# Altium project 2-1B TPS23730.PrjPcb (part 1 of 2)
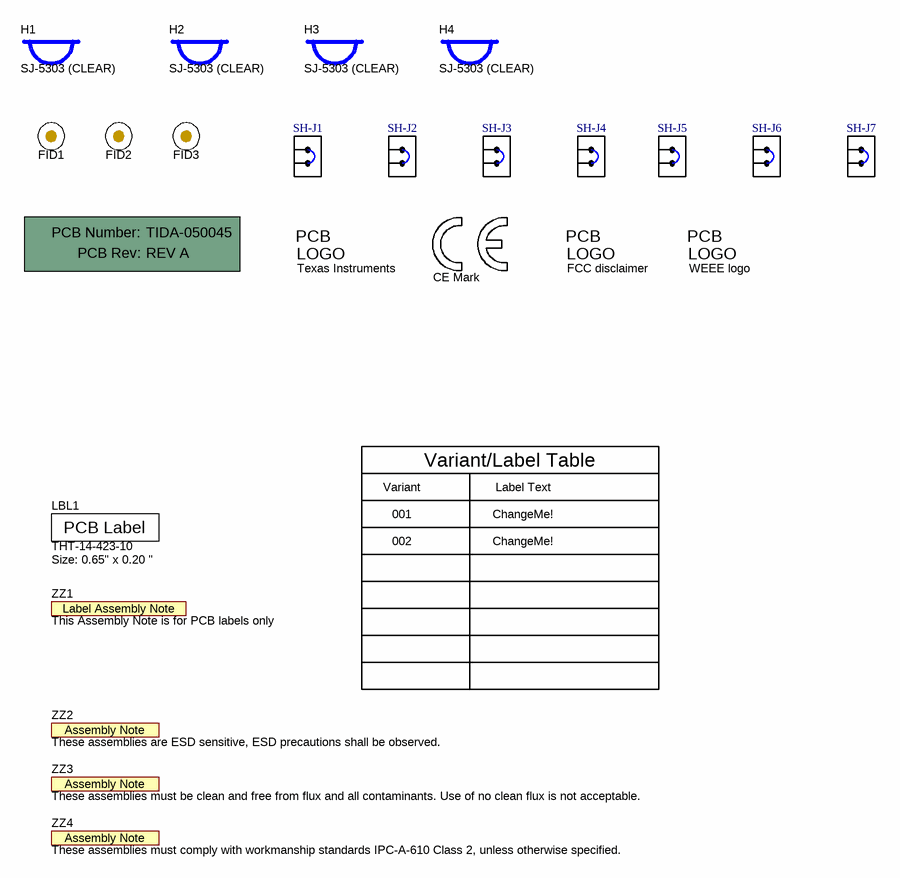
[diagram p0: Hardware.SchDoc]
CopyrightYear: 2020; PCB_Layout: Michael Pahl; PCB_Rev: REV A; PRJ_Customer: Public Release; PRJ_Engineer: Michael Pahl; PRJ_Number: TIDA-050045; PRJ_Title: Type 3 IEEE802.3bt-ready ACF PoE PD; SCH_Rev: A; TechSupport: http://www.ti.com/support; TID: TIDA-050045
3 sheets, 250 parts. Net scope: global (net labels, ports and power ports of the same name join across sheets).
Board file: PCB.PcbDoc
Sheets:
  Hardware.SchDoc
  Power Stage.SchDoc
  TPS23730 Page 1 Input Power.SchDoc

## Sheet Hardware.SchDoc
size 431 x 279 mm; Date: Not shown in title block; ApprovedBy: Not shown in title block; CheckedBy: Not shown in title block; Author: Not shown in title block; CompanyName: Not shown in title block; Engineer: Not shown in title block; Organization: Not shown in title block; Address1: Not shown in title block; Address2: Not shown in title block; Address3: Not shown in title block; Address4: Not shown in title block; DocumentNumber: 3; Revision: Use project parameter SCH_Rev; SheetNumber: 3; SheetTotal: 3; PageSetup: Record=PageOptions¦CenterHorizontal=True¦CenterVertical=True¦PrintScale=1.00¦XCorrection=1.00¦YCorrection=1.00¦PrintKind=0¦BorderSize=5000000¦LeftOffset=0¦BottomOffset=0¦Orientation=2¦PaperLength=1000¦PaperWidth=1000¦Scale=100¦PaperSource=15¦PrintQuality=600¦MediaType=1¦DitherType=10¦PaperKind=Letter¦PrintScaleMode=1

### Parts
!PCB1  Printed Circuit Board  (value not drawn)  (mechanical)
FID1  Fiducial  [Fiducial10-20]  (value not drawn)
FID2  Fiducial  [Fiducial10-20]  (value not drawn)
FID3  Fiducial  [Fiducial10-20]  (value not drawn)
H1  SJ-5303 (CLEAR)  [Bumpon_SJ5003Transparent]
H2  SJ-5303 (CLEAR)  [Bumpon_SJ5003Transparent]
H3  SJ-5303 (CLEAR)  [Bumpon_SJ5003Transparent]
H4  SJ-5303 (CLEAR)  [Bumpon_SJ5003Transparent]
LBL1  THT-14-423-10  Note: Size: 0.65" x 0.20 "  [Label_650x200]
Logo1  CE Mark  [CE_Mark_5mm]  (no BOM)
Logo2  Texas Instruments  [TI_Stacked_Overlay_Small]  (no BOM)
Logo3  FCC disclaimer  [FCC_disclaimer]  (no BOM)
Logo4  WEEE logo  [WEEE_Minimum]  (no BOM)
SH-J1  60900213421  [Wurth_60900213421]  (value not drawn)
SH-J2  60900213421  [Wurth_60900213421]  (value not drawn)
SH-J3  60900213421  [Wurth_60900213421]  (value not drawn)
SH-J4  60900213421  [Wurth_60900213421]  (value not drawn)
SH-J5  60900213421  [Wurth_60900213421]  (value not drawn)
SH-J6  60900213421  [Wurth_60900213421]  (value not drawn)
SH-J7  60900213421  [Wurth_60900213421]  (value not drawn)
ZZ1  This Assembly Note is for PCB labels only  [AssemblyNoteLabel]  (no BOM)
ZZ2  These assemblies are ESD sensitive, ESD precautions shall be observed.  [AssemblyNote]  (no BOM)
ZZ3  These assemblies must be clean and free from flux and all contaminants. Use of no clean flux is not acceptable.  [AssemblyNote]  (no BOM)
ZZ4  These assemblies must comply with workmanship standards IPC-A-610 Class 2, unless otherwise specified.  [AssemblyNote]  (no BOM)

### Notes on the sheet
- Variant
- Variant/Label Table
- Label Text
- 001
- 002
- ChangeMe!

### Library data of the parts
!PCB1 = CMP-0003618-2: Manufacturer: Any; PartNumber: TIDA-050045
FID1-FID3 = CMP-0077181-1: Fiducial mark.  There is nothing to buy or mount.
H1-H4 = CMP-0003620-1: Bumpon, Hemisphere, 0.44 X 0.20, Clear; Manufacturer: 3M
LBL1 = CMP-0003625-1: Thermal Transfer Printable Labels, 0.650" W x 0.200" H - 10,000 per roll; Manufacturer: Brady; CompType: Label
Logo1 = CMP-0074844-1: SymbolCreator: a0412235
Logo2 = CMP-0074838-1: Texas Instrument Corporate Signature; SymbolCreator: a0412235; Lib Reference: TI_Logo; Library Reference: Logo
Logo3 = CMP-0074847-1: FCC_disclaimer; Library Reference: Logo
Logo4 = CMP-0074769-1
SH-J1-SH-J7 = CMP-0003761-2: Shunt, 2.54mm, Gold, Black; Manufacturer: Wurth Elektronik
ZZ1 = CMP-0003616-3
ZZ2 = CMP-0077236-1
ZZ3 = CMP-0077237-1
ZZ4 = CMP-0077238-1

## Sheet Power Stage.SchDoc
size A2; Date: Not shown in title block; ApprovedBy: Not shown in title block; CheckedBy: Not shown in title block; Author: Not shown in title block; CompanyName: Not shown in title block; Engineer: Not shown in title block; Organization: Not shown in title block; Address1: Not shown in title block; Address2: Not shown in title block; Address3: Not shown in title block; Address4: Not shown in title block; DocumentNumber: 2; Revision: Use project parameter SCH_Rev; SheetNumber: 2; SheetTotal: 3; PageSetup: Record=PageOptions¦CenterHorizontal=True¦CenterVertical=True¦PrintScale=1.00¦XCorrection=1.00¦YCorrection=1.00¦PrintKind=0¦BorderSize=5000000¦LeftOffset=0¦BottomOffset=0¦Orientation=2¦PaperLength=1000¦PaperWidth=1000¦Scale=100¦PaperSource=15¦PrintQuality=600¦MediaType=1¦DitherType=10¦PaperKind=Letter¦PrintScaleMode=1
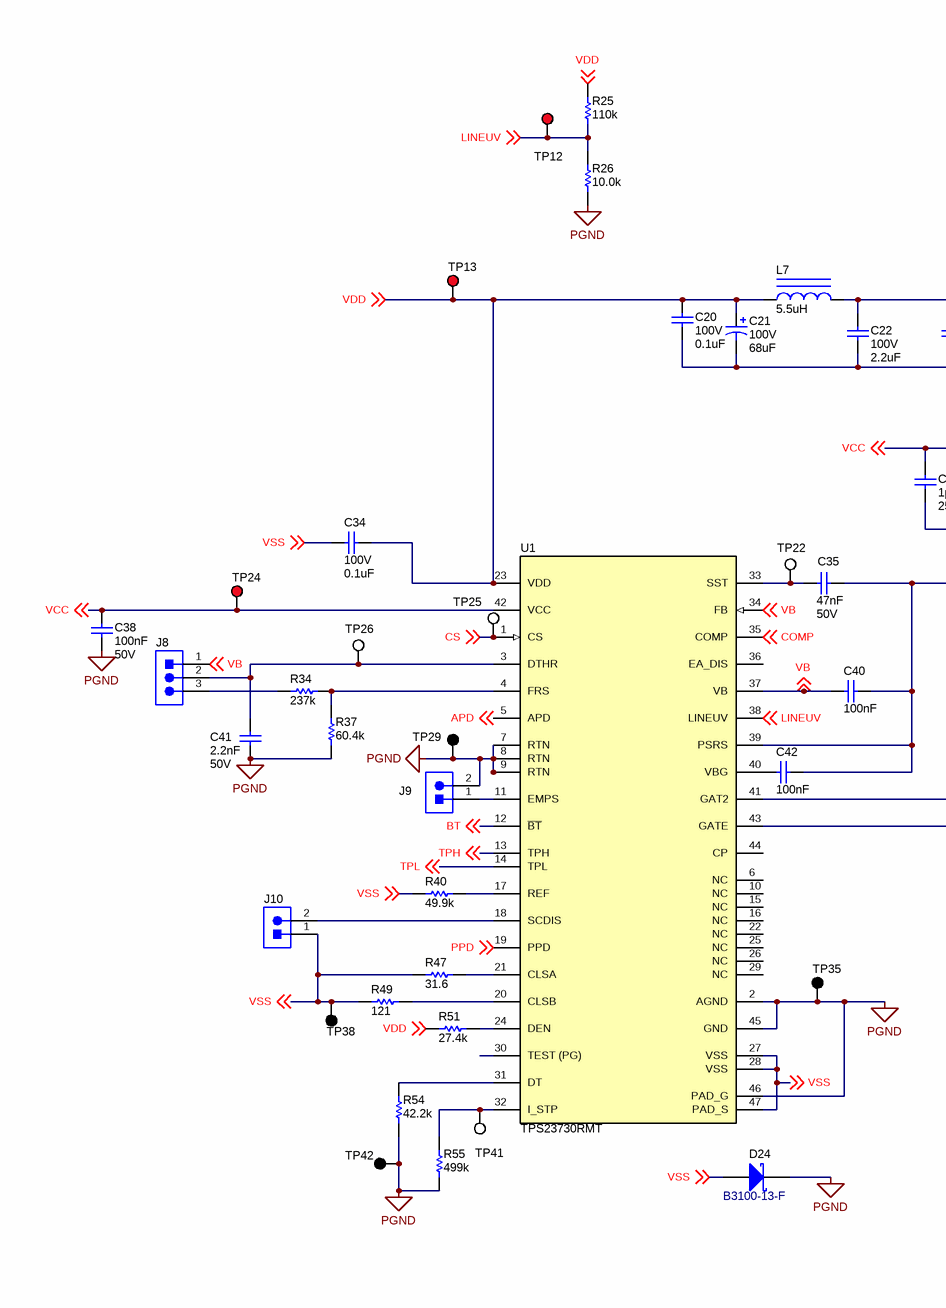
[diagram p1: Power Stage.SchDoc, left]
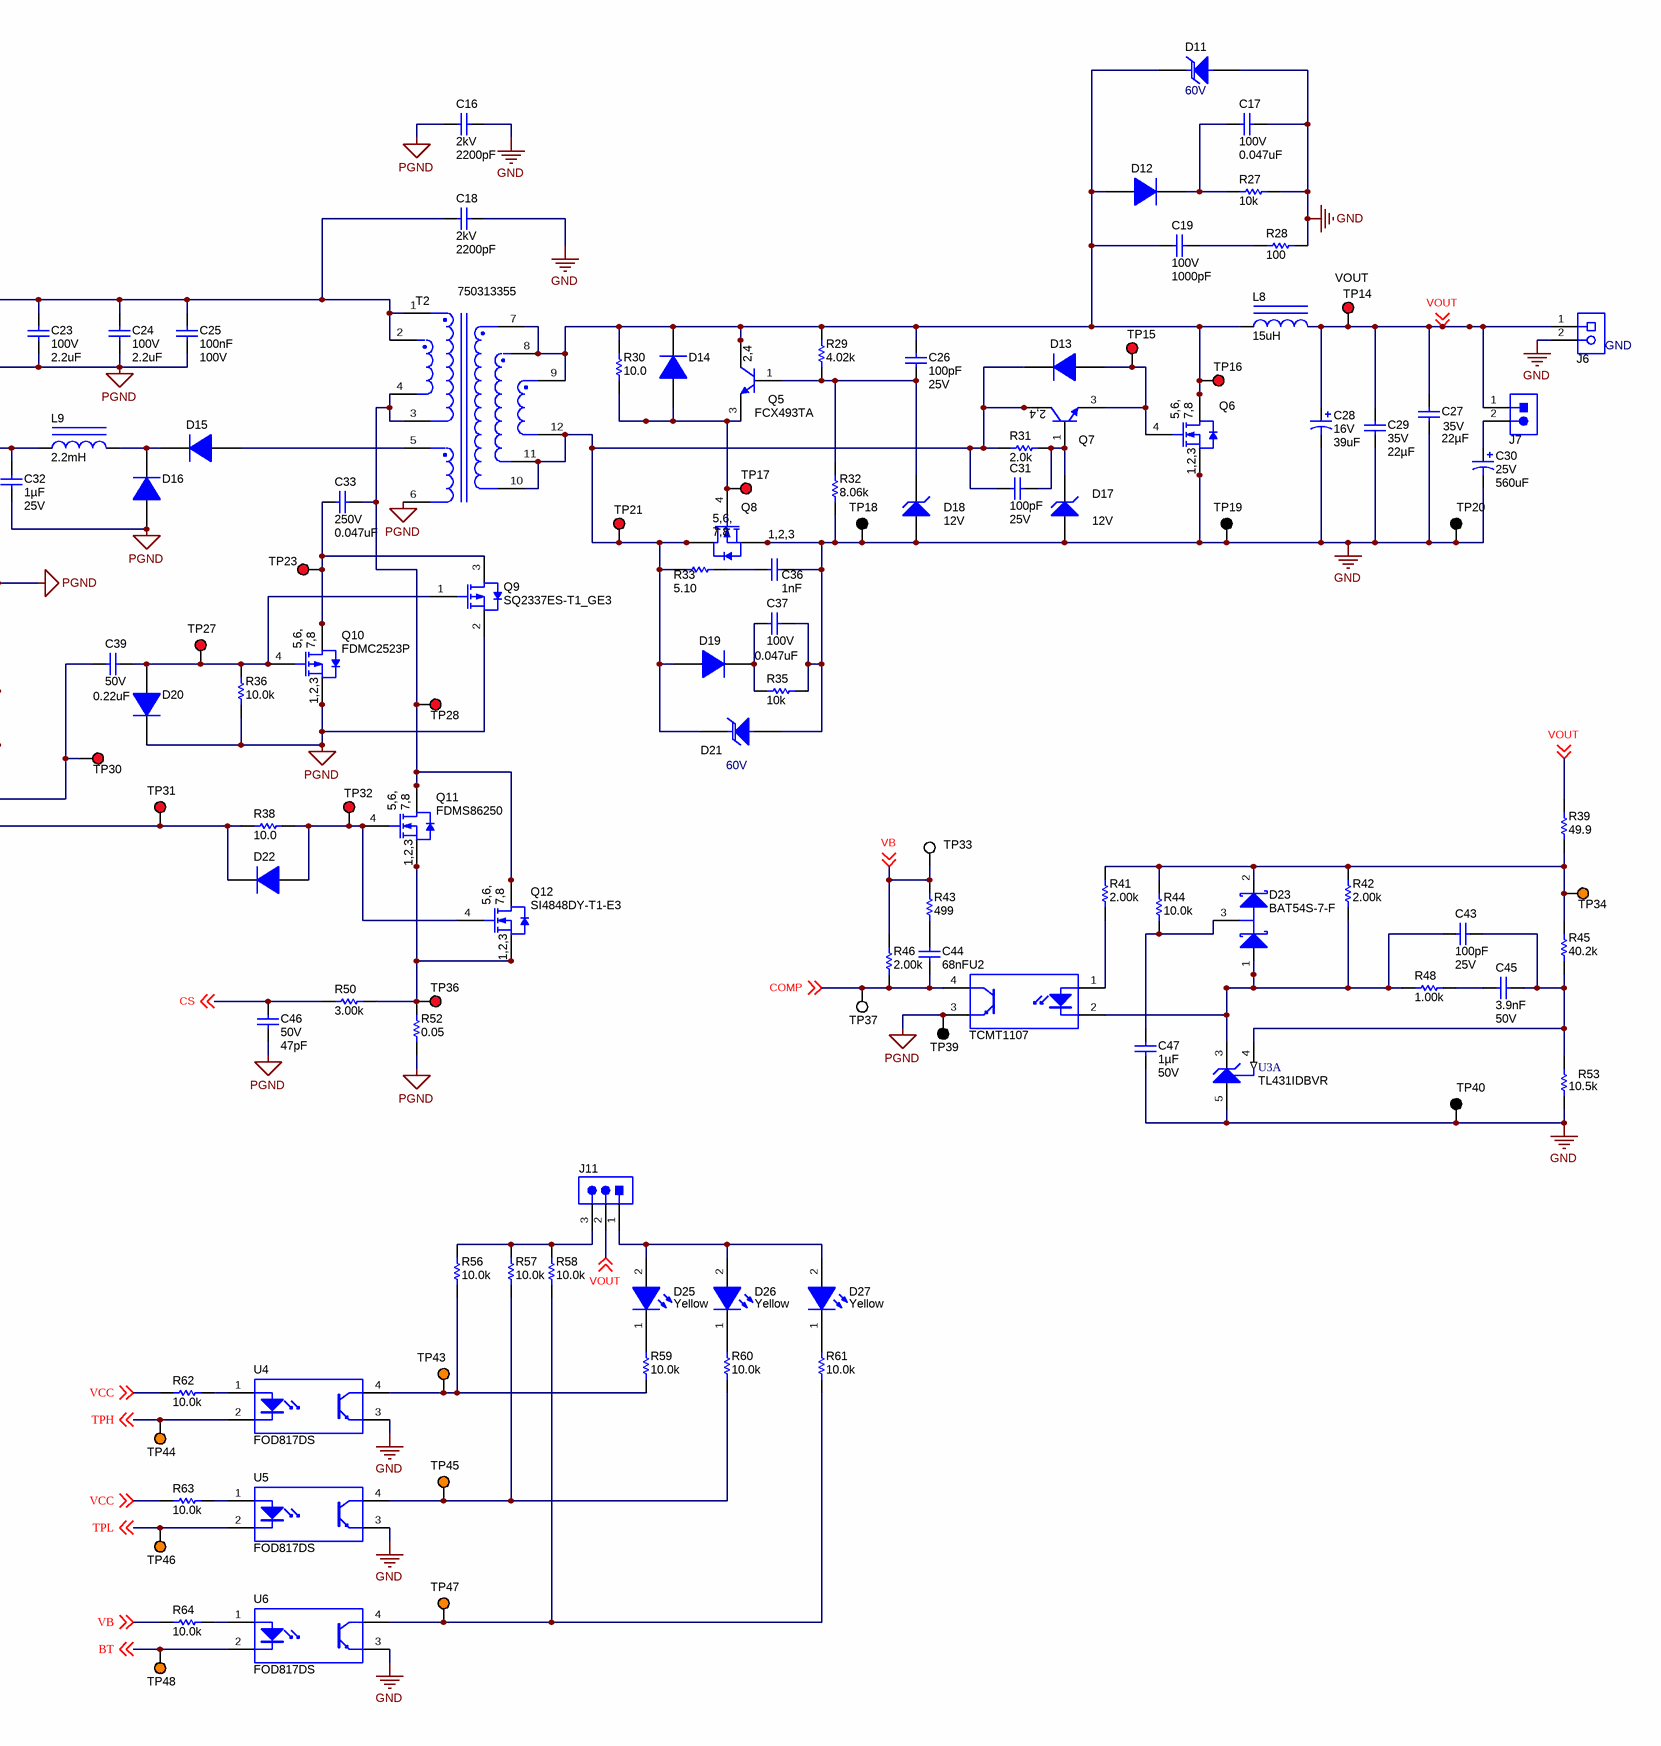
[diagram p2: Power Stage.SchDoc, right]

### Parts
C16  VDC_V: 2kV  ValueDisplayed: 2200pF  [1812_HV]  (hidden comment: C4532X7R3D222K130KA)
C17  VDC_V: 100V  ValueDisplayed: 0.047uF  [1206]  (hidden comment: CGA5H2X7R2A473K115AA)
C18  VDC_V: 2kV  ValueDisplayed: 2200pF  [1812_HV]  (hidden comment: C4532X7R3D222K130KA)
C19  VDC_V: 100V  ValueDisplayed: 1000pF  [1206]  (hidden comment: 12061C102KAT2A)
C20  VDC_V: 100V  ValueDisplayed: 0.1uF  [1206]  (hidden comment: GRM319R72A104KA01D)
C21  VDC_V: 100V  ValueDisplayed: 68uF  [SM_RADIAL_H13]  (hidden comment: EEV-FK2A680Q)
C22  VDC_V: 100V  ValueDisplayed: 2.2uF  [1210_270]  (hidden comment: GRM32ER72A225KA35L)
C23  VDC_V: 100V  ValueDisplayed: 2.2uF  [1210_270]  (hidden comment: GRM32ER72A225KA35L)
C24  VDC_V: 100V  ValueDisplayed: 2.2uF  [1210_270]  (hidden comment: GRM32ER72A225KA35L)
C25  Cap_F: 100nF  VDC_V: 100V  [0805_HV]  (hidden comment: GRM21BR72A104KAC4L)
C26  Cap_F: 100pF  VDC_V: 25V  [0603]  (hidden comment: 06033C101KAT2A)
C27  VDC_V: 35V  ValueDisplayed: 22µF  [1210]  (hidden comment: GMK325BJ226MM-P)
C28  VDC_V: 16V  ValueDisplayed: 39uF  [SM_RADIAL_6.3AMM]  (hidden comment: 16SVP39M)
C29  VDC_V: 35V  ValueDisplayed: 22µF  [1210]  (hidden comment: GMK325BJ226MM-P)
C30  VDC_V: 25V  ValueDisplayed: 560uF  [Panasonic_G]  (hidden comment: EEEFPE561UAP)
C31  Cap_F: 100pF  VDC_V: 25V  [0603]  (hidden comment: 06033C101KAT2A)
C32  Cap_F: 1µF  VDC_V: 25V  [0805_HV]  (hidden comment: GRM21BR71E105KA99L)
C33  VDC_V: 250V  ValueDisplayed: 0.047uF  [1206_180]  (hidden comment: GRM31CR72E473KW03L)
C34  VDC_V: 100V  ValueDisplayed: 0.1uF  [1206]  (hidden comment: GRM319R72A104KA01D)
C35  Cap_F: 47nF  VDC_V: 50V  [0603]  (hidden comment: GRM188R71H473KA61D)
C36  Cap_F: 1nF  [0603]  (hidden comment: CGA3E2X7R2A102K080AA)
C37  VDC_V: 100V  ValueDisplayed: 0.047uF  [1206]  (hidden comment: CGA5H2X7R2A473K115AA)
C38  Cap_F: 100nF  VDC_V: 50V  [0805_HV]  (hidden comment: GCM21BR71H104KA37K)
C39  VDC_V: 50V  ValueDisplayed: 0.22uF  [0805_HV]  (hidden comment: C2012X5R1H224K125AA)
C40  Cap_F: 100nF  [0603]  (hidden comment: CGA3E2X7R1E104K080AA)
C41  Cap_F: 2.2nF  VDC_V: 50V  [0603]  (hidden comment: C0603C222K5RAC)
C42  Cap_F: 100nF  [0603]  (hidden comment: C0603C104J3RACTU)
C43  Cap_F: 100pF  VDC_V: 25V  [0603]  (hidden comment: 06033C101KAT2A)
C44  Cap_F: 68nF  [0603]  (hidden comment: GRM188R71C683KA01D)
C45  Cap_F: 3.9nF  VDC_V: 50V  [0603]  (hidden comment: GRM188R71H392KA01D)
C46  VDC_V: 50V  ValueDisplayed: 47pF  [0603]  (hidden comment: GRM1885C1H470JA01D)
C47  Cap_F: 1µF  VDC_V: 50V  [0805_HV]  (hidden comment: C2012X7R1H105K125AB)
D11  value 60V  [SMC]  (hidden comment: SMCJ60A)
D12  MURA110T3G  [SMA]  (value not drawn)
D13  MMSD914T1G  [SOD-123]  (value not drawn)
D14  MMSD914T1G  [SOD-123]  (value not drawn)
D15  MMSD914T1G  [SOD-123]  (value not drawn)
D16  MMSD914T1G  [SOD-123]  (value not drawn)
D17  value 12V  [SOD-123]  (hidden comment: MMSZ5242B-7-F)
D18  value 12V  [SOD-123]  (hidden comment: MMSZ5242B-7-F)
D19  MURA110T3G  [SMA]  (value not drawn)
D20  MMSD914T1G  [SOD-123]  (value not drawn)
D21  value 60V  [SMC]  (hidden comment: SMCJ60A)
D22  MMSD914T1G  [SOD-123]  (value not drawn)
D23  BAT54S-7-F  [SOT-23]
D24  B3100-13-F  [SMC]
D25  value Yellow  [WL-SMCW_YELLOW]  (hidden comment: 150060YS75000)
D26  value Yellow  [WL-SMCW_YELLOW]  (hidden comment: 150060YS75000)
D27  value Yellow  [WL-SMCW_YELLOW]  (hidden comment: 150060YS75000)
J6  ED555/2DS  [TERM_BLK_ED555-2DS]  (value not drawn)
J7  5-146278-2  [TE_5-146278-2]  (value not drawn)
J8  5-146278-3  [TE_5-146278-3]  (value not drawn)
J9  5-146278-2  [TE_5-146278-2]  (value not drawn)
J10  5-146278-2  [TE_5-146278-2]  (value not drawn)
J11  5-146278-3  [TE_5-146278-3]  (value not drawn)
L7  ValueDisplayed: 5.5uH  [WE-HC6]  (hidden comment: 744325550)
L8  ValueDisplayed: 15uH  [WE-HCB_1890]  (hidden comment: 74435571500)
L9  ValueDisplayed: 2.2mH  [WE-PD2-L]  (hidden comment: 768775322)
Q5  FCX493TA  [SOT-89-3]
Q6  BSC105N10LSF G  [PG-TDSON-8]  (value not drawn)
Q7  FCX493TA  [SOT-89-3]  (value not drawn)
Q8  BSC105N10LSF G  [PG-TDSON-8]  (value not drawn)
Q9  SQ2337ES-T1_GE3  [SOT-23]
Q10  FDMC2523P  [MLP08S]
Q11  FDMS86250  [TRANS_Fairchild_PQFN08A]
Q12  SI4848DY-T1-E3  [SOIC-8]
R25  ValueDisplayed: 110k  [0603]  (hidden comment: CRCW0603110KFKEA)
R26  ValueDisplayed: 10.0k  [0603]  (hidden comment: CRCW060310K0FKEA)
R27  ValueDisplayed: 10k  [2512]  (hidden comment: CRCW251210K0JNEG)
R28  ValueDisplayed: 100  [2512]  (hidden comment: CRCW2512100RJNEG)
R29  ValueDisplayed: 4.02k  [1206]  (hidden comment: CRCW12064K02FKEA)
R30  ValueDisplayed: 10.0  [0603]  (hidden comment: CRCW060310R0FKEAHP)
R31  ValueDisplayed: 2.0k  [0603]  (hidden comment: CRCW06032K00JNEA)
R32  ValueDisplayed: 8.06k  [1206]  (hidden comment: CRCW12068K06FKEA)
R33  ValueDisplayed: 5.10  [0805_HV]  (hidden comment: ERJ-6RQF5R1V)
R34  ValueDisplayed: 237k  [0603]  (hidden comment: RC0603FR-07237KL)
R35  ValueDisplayed: 10k  [2512]  (hidden comment: CRCW251210K0JNEG)
R36  ValueDisplayed: 10.0k  [0603]  (hidden comment: CRCW060310K0FKEA)
R37  ValueDisplayed: 60.4k  [0603]  (hidden comment: CRCW060360K4FKEA)
R38  ValueDisplayed: 10.0  [0603]  (hidden comment: CRCW060310R0FKEA)
R39  ValueDisplayed: 49.9  [0603]  (hidden comment: RC0603FR-0749R9L)
R40  ValueDisplayed: 49.9k  [0603]  (hidden comment: CRCW060349K9FKEA)
R41  ValueDisplayed: 2.00k  [0603]  (hidden comment: CRCW06032K00FKEA)
R42  ValueDisplayed: 2.00k  [VSMP_0603]  (hidden comment: Y16362K00000F9R)
R43  ValueDisplayed: 499  [0603]  (hidden comment: CRCW0603499RFKEA)
R44  ValueDisplayed: 10.0k  [0603]  (hidden comment: CRCW060310K0FKEA)
R45  ValueDisplayed: 40.2k  [0603]  (hidden comment: CRCW060340K2FKEA)
R46  ValueDisplayed: 2.00k  [0603]  (hidden comment: CRCW06032K00FKEA)
R47  ValueDisplayed: 31.6  [0805_HV]  (hidden comment: CRCW080531R6FKEA)
R48  ValueDisplayed: 1.00k  [0603]  (hidden comment: CRCW06031K00FKEA)
R49  ValueDisplayed: 121  [0805_HV]  (hidden comment: CRCW0805121RFKEA)
R50  ValueDisplayed: 3.00k  [0603]  (hidden comment: RC0603FR-073KL)
R51  ValueDisplayed: 27.4k  [0603]  (hidden comment: RC0603FR-0727K4L)
R52  ValueDisplayed: 0.05  [1206]  (hidden comment: ERJ-8CWFR050V)
R53  ValueDisplayed: 10.5k  [0603]  (hidden comment: CRCW060310K5FKEA)
R54  ValueDisplayed: 42.2k  [0603]  (hidden comment: CRCW060342K2FKEA)
R55  ValueDisplayed: 499k  [0603]  (hidden comment: CRCW0603499KFKEA)
R56  ValueDisplayed: 10.0k  [0603]  (hidden comment: CRCW060310K0FKEA)
R57  ValueDisplayed: 10.0k  [0603]  (hidden comment: CRCW060310K0FKEA)
R58  ValueDisplayed: 10.0k  [0603]  (hidden comment: CRCW060310K0FKEA)
R59  ValueDisplayed: 10.0k  [0603]  (hidden comment: CRCW060310K0FKEA)
R60  ValueDisplayed: 10.0k  [0603]  (hidden comment: CRCW060310K0FKEA)
R61  ValueDisplayed: 10.0k  [0603]  (hidden comment: CRCW060310K0FKEA)
R62  ValueDisplayed: 10.0k  [0603L]  (hidden comment: CRCW060310K0FKEA)
R63  ValueDisplayed: 10.0k  [0603L]  (hidden comment: CRCW060310K0FKEA)
R64  ValueDisplayed: 10.0k  [0603L]  (hidden comment: CRCW060310K0FKEA)
T2  750313355  [FP-750313355_SMT_XFRMR_29MM08_23MM1-MFG]
TP12  DRAIN_S  [Keystone5000]  (value not drawn)
TP13  GATE  [Keystone5000]  (value not drawn)
TP14  VOUT  [Keystone5000]
TP15  GATE_P  [Keystone5000]  (value not drawn)
TP16  DRAIN_P  [Keystone5000]  (value not drawn)
TP17  GATE_S  [Keystone5000]  (value not drawn)
TP18  GND  [Keystone5001]  (value not drawn)
TP19  GND  [Keystone5001]  (value not drawn)
TP20  GND  [Keystone5001]  (value not drawn)
TP21  DRAIN_S  [Keystone5000]  (value not drawn)
TP22  SST  [Keystone5002]  (value not drawn)
TP23  GAT2  [Keystone5000]  (value not drawn)
TP24  GATE  [Keystone5000]  (value not drawn)
TP25  SST  [Keystone5002]  (value not drawn)
TP26  SST  [Keystone5002]  (value not drawn)
TP27  GAT2  [Keystone5000]  (value not drawn)
TP28  DRAIN_S  [Keystone5000]  (value not drawn)
TP29  RTN  [Keystone5001]  (value not drawn)
TP30  GAT2  [Keystone5000]  (value not drawn)
TP31  GATE  [Keystone5000]  (value not drawn)
TP32  GATE  [Keystone5000]  (value not drawn)
TP33  I_STP  [Keystone5002]  (value not drawn)
TP34  TEST (PG)  [Keystone5003]  (value not drawn)
TP35  RTN  [Keystone5001]  (value not drawn)
TP36  SOURCE  [Keystone5000]  (value not drawn)
TP37  I_STP  [Keystone5002]  (value not drawn)
TP38  (no value)  [Keystone5001]
TP39  RTN  [Keystone5001]  (value not drawn)
TP40  GND  [Keystone5001]  (value not drawn)
TP41  I_STP  [Keystone5002]  (value not drawn)
TP42  RTN  [Keystone5001]  (value not drawn)
TP43  TEST (PG)  [Keystone5003]  (value not drawn)
TP44  TEST (PG)  [Keystone5003]  (value not drawn)
TP45  TEST (PG)  [Keystone5003]  (value not drawn)
TP46  TEST (PG)  [Keystone5003]  (value not drawn)
TP47  TEST (PG)  [Keystone5003]  (value not drawn)
TP48  TEST (PG)  [Keystone5003]  (value not drawn)
U1  TPS23730RMT  [RMT0045A]
U2  TCMT1107  [SOP-4]
U3  TL431IDBVR  [DBV0005A_M]  (part A of 2)
U4  FOD817DS  [N04C]
U5  FOD817DS  [N04C]
U6  FOD817DS  [N04C]

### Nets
GND: C16.1 C17.1 C18.1 C27.1 C28.2(-) C29.1 C30.2(-) C36.1 C37.1 C47.2 D11.2(A) D17.2(A) D18.2(A) D21.2(A) J6.2 Q6.1(S) Q6.2(S) Q6.3(S) Q8.1(S) Q8.2(S) Q8.3(S) R27.2 R28.2 R32.1 R35.2 R53.2 TP18.1 TP19.1 TP20.1 TP40.1 U3.5(ANODE) U4.3(E) U5.3(E) U6.3(E)
PGND: C16.2 C20.2 C21.2(-) C22.2 C23.2 C24.2 C25.2 C32.2 C35.1 C38.2 C40.1 C41.2 C42.1 C46.2 D16.2(A) D20.1(K) D24.1(K) J9.2 Q9.2(S) Q10.1(S) Q10.2(S) Q10.3(S) R26.1 R36.1 R37.1 R52.1 R54.1 R55.1 T2.6 TP29.1 TP35.1 TP39.1 TP42.1 U1.2(AGND) U1.7(RTN) U1.8(RTN) U1.9(RTN) U1.39(PSRS) U1.45(GND) U1.46(PAD_G) U2.3(E)
APD: U1.5(APD) ; off-sheet APD
BT: TP48.1 U1.12(~{BT}) U6.2(K) ; off-sheet BT
COMP: C44.1 R46.1 TP37.1 U1.35(COMP) U2.4(C) ; off-sheet COMP
CS: C46.1 R50.1 TP25.1 U1.1(CS) ; off-sheet CS
LINEUV: R25.1 R26.2 TP12.1 U1.38(LINEUV) ; off-sheet LINEUV
PPD: U1.19(PPD) ; off-sheet PPD
TPH: TP44.1 U1.13(TPH) U4.2(K) ; off-sheet TPH
TPL: TP46.1 U1.14(TPL) U5.2(K) ; off-sheet TPL
VB: C40.2 J8.1 R43.2 R46.2 R64.2 TP33.1 U1.34(FB) U1.37(VB) ; off-sheet VB
VCC: C32.1 C38.1 L9.1 R62.2 R63.2 TP24.1 U1.42(VCC) ; off-sheet VCC
VDD: C20.1 C21.1(+) C34.1 L7.1 R25.2 R51.1 TP13.1 U1.23(VDD) ; off-sheet VDD
VOUT: C27.2 C28.1(+) C29.2 J6.1 J7.1 J11.2 L8.2 R39.2 TP14.1 ; off-sheet VOUT
VSS: C34.2 D24.2(A) J10.1 R40.1 R47.1 R49.1 TP38.1 U1.27(VSS) U1.28(VSS) U1.47(PAD_S) ; off-sheet VSS
NetC17_2: C17.2 D12.1(K) R27.1
NetC18_2: C18.2 C22.1 C23.1 C24.1 C25.1 L7.2 T2.1 T2.2
NetC19_1: C19.1 R28.1
NetC19_2: C19.2 C26.2 D11.1(K) D12.2(A) D14.1(K) L8.1 Q5.2(C) Q5.4(C) Q6.5(D) Q6.6(D) Q6.7(D) Q6.8(D) Q6.9(D) R29.2 R30.2 T2.7 T2.8 T2.9 TP16.1
NetC26_1: C26.1 D18.1(K) Q5.1(B) R29.1 R32.2
NetC30_1: C30.1(+) J7.2
NetC31_1: C31.1 D13.1(K) D19.2(A) D21.1(K) Q7.2(C) Q7.4(C) Q8.5(D) Q8.6(D) Q8.7(D) Q8.8(D) Q8.9(D) R31.2 R33.1 T2.10 T2.11 T2.12 TP21.1
NetC31_2: C31.2 D17.1(K) Q7.1(B) R31.1
NetC33_1: C33.1 Q11.5(D) Q11.6(D) Q11.7(D) Q11.8(D) Q12.5(D) Q12.6(D) Q12.7(D) Q12.8(D) T2.3 T2.4 TP28.1
NetC33_2: C33.2 Q9.3(D) Q10.5(D) Q10.6(D) Q10.7(D) Q10.8(D) TP23.1
NetC35_2: C35.2 TP22.1 U1.33(SST)
NetC36_2: C36.2 R33.2
NetC37_2: C37.2 D19.1(K) R35.1
NetC39_1: C39.1 D20.2(A) Q9.1(G) Q10.4(G) R36.2 TP27.1
NetC39_2: C39.2 TP30.1 U1.41(GAT2)
NetC41_1: C41.1 J8.2 TP26.1 U1.3(DTHR)
NetC42_2: C42.2 U1.40(VBG)
NetC43_1: C43.1 D23.1(A) R42.1 R48.1 U2.2(K) U3.3(CATHODE)
NetC43_2: C43.2 C45.1 R45.2 R53.1 U3.4(REF)
NetC44_2: C44.2 R43.1
NetC45_2: C45.2 R48.2
NetC47_1: C47.1 D23.3(C) R44.1
NetD13_2: D13.2(A) Q6.4(G) Q7.3(E) TP15.1
NetD14_2: D14.2(A) Q5.3(E) Q8.4(G) R30.1 TP17.1
NetD15_1: D15.1(K) D16.1(K) L9.2
NetD15_2: D15.2(A) T2.5
NetD22_1: D22.1(K) R38.1 TP31.1 U1.43(GATE)
NetD22_2: D22.2(A) Q11.4(G) Q12.4(G) R38.2 TP32.1
NetD23_2: D23.2(K) R39.1 R41.2 R42.2 R44.2 R45.1 TP34.1
NetD25_1: D25.1(K) R59.2
NetD25_2: D25.2(A) D26.2(A) D27.2(A) J11.1
NetD26_1: D26.1(K) R60.2
NetD27_1: D27.1(K) R61.2
NetJ8_3: J8.3 R34.1
NetJ9_1: J9.1 U1.11(EMPS)
NetJ10_2: J10.2 U1.18(SCDIS)
NetJ11_3: J11.3 R56.2 R57.2 R58.2
NetQ11_1: Q11.1(S) Q11.2(S) Q11.3(S) Q12.1(S) Q12.2(S) Q12.3(S) R50.2 R52.2 TP36.1
NetR34_2: R34.2 R37.2 U1.4(FRS)
NetR40_2: R40.2 U1.17(REF)
NetR41_1: R41.1 U2.1(A)
NetR47_2: R47.2 U1.21(CLSA)
NetR49_2: R49.2 U1.20(CLSB)
NetR51_2: R51.2 U1.24(DEN)
NetR54_2: R54.2 U1.31(DT)
NetR55_2: R55.2 TP41.1 U1.32(I_STP)
NetR56_1: R56.1 R59.1 TP43.1 U4.4(C)
NetR57_1: R57.1 R60.1 TP45.1 U5.4(C)
NetR58_1: R58.1 R61.1 TP47.1 U6.4(C)
NetR62_1: R62.1 U4.1(A)
NetR63_1: R63.1 U5.1(A)
NetR64_1: R64.1 U6.1(A)

Not connected (* = marked no-connect by the designer): U1 6(NC) 10(NC) 15(NC) 16(NC) 22(NC) 25(NC) 26(NC) 29(NC) 30(TEST_(PG)) 36(EA_DIS) 44(CP)

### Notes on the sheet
- (near J6) GND

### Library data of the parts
C16 C18 = CMP-0009358-2: CAP, CERM, 2200 pF, 2000 V, +/- 10%, X7R, 1812; Manufacturer: TDK; TaMin_C: -55°C; Polarized: N; SizeAreaWB_mm2: 23.1; Value1: Unknown; U/M: EA; Value: 2200pF; TaMax_C: 125°C; SizeZ_mm: 1.35; SizeX_mm: 4.5; SizeY_mm: 3.2; Cap_Case: 1812; Value2: 2000V; SizeArea_mm2: 14.4; Cap_F: 2.2nF; AEC Category: Q200
C17 C37 = CMP-0008768-2: CAP, CERM, 0.047 uF, 100 V, +/- 10%, X7R, AEC-Q200 Grade 1, 1206; Manufacturer: TDK; TaMin_C: -55°C; ESR_ohm: 0.065629; Polarized: N; SizeAreaWB_mm2: 10.92; Value1: 0.065629 ohm; U/M: EA; TaMax_C: 125°C; SizeZ_mm: 1.35; SizeX_mm: 3.2; SizeY_mm: 1.6; SizeArea_mm2: 5.12; AEC Qualified: Y; Cap_F: 47nF; IRMS_A: 927.421mA; AEC Grade: 1; AEC Category: Q200
C19 = CMP-0008483-2: CAP, CERM, 1000 pF, 100 V, +/- 10%, X7R, 1206; Manufacturer: AVX; TaMin_C: -55°C; ESR_ohm: 0.427; Polarized: N; SizeAreaWB_mm2: 10.92; Value1: 0.427 ohm; U/M: EA; Value: 1000pF; TaMax_C: 125°C; SizeZ_mm: 1.35; SizeX_mm: 3.2; SizeY_mm: 1.6; SizeArea_mm2: 5.12; Cap_F: 1nF; AEC Category: Q200
C20 C34 = CMP-0008881-2: CAP, CERM, 0.1 uF, 100 V, +/- 10%, X7R, 1206; Manufacturer: MuRata; TaMin_C: -55°C; Polarized: N; SizeAreaWB_mm2: 10.92; Value1: Unknown; U/M: EA; Value: 0.1uF; TaMax_C: 125°C; SizeZ_mm: 1.35; SizeX_mm: 3.2; SizeY_mm: 1.6; SizeArea_mm2: 5.12; Cap_F: 100nF; AEC Category: Q200
C21 = CMP-0011226-2: CAP, AL, 68 uF, 100 V, +/- 20%, 0.32 ohm, AEC-Q200 Grade 2, SMD; Manufacturer: Panasonic; TaMin_C: -55°C; ESR_ohm: 0.32; Polarized: Y; SizeAreaWB_mm2: 263.5; U/M: EA; Value: 68uF; TaMax_C: 105°C; SizeZ_mm: 13.5; SizeX_mm: 15; Cap_Case: H13; SizeArea_mm2: 202.5; CompType: Capacitor; Cap_F: 68µF; IRMS_A: 500mA; AEC Grade: 2; AEC Category: Q200
C22-C24 = CMP-0009232-2: CAP, CERM, 2.2 uF, 100 V, +/- 10%, X7R, 1210; Manufacturer: MuRata; TaMin_C: -55°C; ESR_ohm: 7m; Polarized: N; SizeAreaWB_mm2: 14.7; Value1: 0.007 ohm; U/M: EA; Value: 2.2uF; TaMax_C: 125°C; SizeZ_mm: 2.7; SizeX_mm: 3.2; SizeY_mm: 2.5; Cap_Case: 1210; SizeArea_mm2: 8; Cap_F: 2.2µF; IRMS_A: 4.4A; AEC Category: Q200
C25 = CMP-0008363-2: CAP, CERM, 0.1 uF, 100 V, +/- 10%, X7R, 0805; Manufacturer: MuRata; TaMin_C: -55°C; Polarized: N; SizeAreaWB_mm2: 6.75; Value1: Unknown; U/M: EA; Value: 0.1uF; TaMax_C: 125°C; SizeZ_mm: 1.45; SizeX_mm: 2; SizeY_mm: 1.25; Cap_Case: 0805; SizeArea_mm2: 2.5; AEC Category: Q200
C26 C31 C43 = CMP-0006751-4: CAP, CERM, 100 pF, 25 V, +/- 10%, X7R, 0603; Manufacturer: AVX; TaMin_C: -55°C; Polarized: N; SizeAreaWB_mm2: 4.68; Value1: Unknown; U/M: EA; Value: 100pF; TaMax_C: 125°C; SizeZ_mm: 1; SizeX_mm: 1.6; SizeY_mm: 0.8; SizeArea_mm2: 1.28; AEC Category: Q200
C27 C29 = CMP-0085817-1: CAP, CERM, 22 µF, 35 V,+/- 20%, X5R, 1210; Manufacturer: Taiyo Yuden; Value: 22uF; SizeZ_mm: 1.35; TaMax_C: 85°C; U/M: EA; SizeAreaWB_mm2: 14.7; SizeX_mm: 3.2; SizeArea_mm2: 8; TaMin_C: -55°C; AEC Qualified: N; SizeY_mm: 2.5; AEC Category: Q200
C28 = CMP-0012085-3: CAP, Aluminum Polymer, 39 uF, 16 V, +/- 20%, 0.05 ohm, 6.3x5.8 SMD; Manufacturer: Panasonic; TaMin_C: -55°C; ESR_ohm: 0.05; Polarized: Y; SizeAreaWB_mm2: 79.98; Value: 39uF; TaMax_C: 105°C; SizeZ_mm: 6; SizeX_mm: 7.3; SizeY_mm: 6.6; Cap_Case: 6.6x6.6x5.9; SizeArea_mm2: 48.18; CompType: Capacitor; Cap_F: 39µF; IRMS_A: 1.62A; AEC Category: Q200
C30 = CMP-0010735-1: CAP, AL, 560 uF, 25 V, +/- 20%, 0.08 ohm, AEC-Q200 Grade 2, SMD; Manufacturer: Panasonic; TaMin_C: -55°C; ESR_ohm: 0.08; Polarized: Y; SizeAreaWB_mm2: 151.29; U/M: EA; Value: 560uF; TaMax_C: 105°C; SizeZ_mm: 10.5; SizeX_mm: 10.3; Cap_Case: 10x10.2mm; SizeArea_mm2: 106.09; CompType: Capacitor; Cap_F: 560µF; IRMS_A: 850mA; AEC Grade: 2; AEC Category: Q200
C32 = CMP-0008336-2: CAP, CERM, 1 uF, 25 V, +/- 10%, X7R, 0805; Manufacturer: MuRata; TaMin_C: -55°C; Polarized: N; SizeAreaWB_mm2: 6.75; Value1: Unknown; U/M: EA; Value: 1uF; TaMax_C: 125°C; SizeZ_mm: 1.45; SizeX_mm: 2; SizeY_mm: 1.25; Cap_Case: 0805; SizeArea_mm2: 2.5; AEC Category: Q200
C33 = CMP-0008975-2: CAP, CERM, 0.047 uF, 250 V, +/- 10%, X7R, 1206; Manufacturer: MuRata; TaMin_C: -55°C; Polarized: N; SizeAreaWB_mm2: 10.92; Value1: Unknown; U/M: EA; TaMax_C: 125°C; SizeZ_mm: 1.8; SizeX_mm: 3.2; SizeY_mm: 1.6; Cap_Case: 1206; SizeArea_mm2: 5.12; Cap_F: 47nF; AEC Category: Q200
C35 = CMP-0007457-4: CAP, CERM, 0.047 uF, 50 V, +/- 10%, X7R, 0603; Manufacturer: MuRata; TaMin_C: -55°C; Polarized: N; SizeAreaWB_mm2: 4.68; Value1: Unknown; U/M: EA; TaMax_C: 125°C; SizeZ_mm: 1; SizeX_mm: 1.6; SizeY_mm: 0.8; SizeArea_mm2: 1.28; AEC Category: Q200
C36 = CMP-0007081-4: CAP, CERM, 1000 pF, 100 V, +/- 10%, X7R, AEC-Q200 Grade 1, 0603; Manufacturer: TDK; TaMin_C: -55°C; ESR_ohm: 1.97137; Polarized: N; SizeAreaWB_mm2: 4.68; Value1: 1.97137 ohm; U/M: EA; Value: 1000pF; TaMax_C: 125°C; SizeZ_mm: 1; SizeX_mm: 1.6; SizeY_mm: 0.8; Value2: 100V; SizeArea_mm2: 1.28; AEC Qualified: Y; IRMS_A: 305.705mA; AEC Category: Q200
C38 = CMP-0008021-2: CAP, CERM, 0.1 uF, 50 V, +/- 10%, X7R, AEC-Q200 Grade 1, 0805; Manufacturer: MuRata; TaMin_C: -55°C; Polarized: N; SizeAreaWB_mm2: 6.75; Value1: Unknown; U/M: EA; Value: 0.1uF; TaMax_C: 125°C; SizeZ_mm: 1.45; SizeX_mm: 2; SizeY_mm: 1.25; Cap_Case: 0805; SizeArea_mm2: 2.5; AEC Qualified: Y; AEC Grade: 1; AEC Category: Q200
C39 = CMP-0007835-2: CAP, CERM, 0.22 uF, 50 V, +/- 10%, X5R, 0805; Manufacturer: TDK; TaMin_C: -55°C; ESR_ohm: 0.016949; Polarized: N; SizeAreaWB_mm2: 6.75; Value1: 0.016949 ohm; U/M: EA; Value: 0.22uF; TaMax_C: 85°C; SizeZ_mm: 1.45; SizeX_mm: 2; Cap_Case: 0805; SizeArea_mm2: 2.5; Cap_F: 220nF; SizeY_mm: 1.25; IRMS_A: 1.59611A; AEC Category: Q200
C40 = CMP-0007077-5: CAP, CERM, 0.1 uF, 25 V, +/- 10%, X7R, AEC-Q200 Grade 1, 0603; Manufacturer: TDK; TaMin_C: -55°C; Polarized: N; SizeAreaWB_mm2: 4.68; Value1: Unknown; U/M: EA; Value: 0.1uF; TaMax_C: 125°C; SizeZ_mm: 1; SizeX_mm: 1.6; SizeY_mm: 0.8; Value2: 25V; SizeArea_mm2: 1.28; AEC Qualified: Y; AEC Category: Q200
C41 = CMP-0006897-4: CAP, CERM, 2200 pF, 50 V, +/- 10%, X7R, 0603; Manufacturer: Kemet; TaMin_C: -55°C; Polarized: N; SizeAreaWB_mm2: 4.68; Value1: Unknown; U/M: EA; Value: 2200pF; TaMax_C: 125°C; SizeZ_mm: 1; SizeX_mm: 1.6; SizeY_mm: 0.8; SizeArea_mm2: 1.28; AEC Category: Q200
C42 = CMP-0006856-6: CAP, CERM, 0.1 uF, 25 V, +/- 5%, X7R, 0603; Manufacturer: Kemet; TaMin_C: -55°C; Polarized: N; SizeAreaWB_mm2: 4.68; Value1: Unknown; U/M: EA; Value: 0.1uF; TaMax_C: 125°C; SizeZ_mm: 1; SizeX_mm: 1.6; SizeY_mm: 0.8; Value2: 25V; SizeArea_mm2: 1.28; AEC Category: Q200
C44 = CMP-0007400-4: CAP, CERM, 0.068 uF, 16 V, +/- 10%, X7R, 0603; Manufacturer: MuRata; TaMin_C: -55°C; Polarized: N; SizeAreaWB_mm2: 4.68; Value1: Unknown; U/M: EA; TaMax_C: 125°C; SizeZ_mm: 1; SizeX_mm: 1.6; SizeY_mm: 0.8; Value2: 16V; SizeArea_mm2: 1.28; AEC Category: Q200
C45 = CMP-0007453-4: CAP, CERM, 3900 pF, 50 V, +/- 10%, X7R, 0603; Manufacturer: MuRata; TaMin_C: -55°C; Polarized: N; SizeAreaWB_mm2: 4.68; Value1: Unknown; U/M: EA; Value: 3900pF; TaMax_C: 125°C; SizeZ_mm: 1; SizeX_mm: 1.6; SizeY_mm: 0.8; SizeArea_mm2: 1.28; AEC Category: Q200
C46 = CMP-0007220-4: CAP, CERM, 47 pF, 50 V, +/- 5%, C0G/NP0, 0603; Manufacturer: MuRata; TaMin_C: -55°C; Polarized: N; SizeAreaWB_mm2: 4.68; Value1: Unknown; U/M: EA; Value: 47pF; TaMax_C: 125°C; SizeZ_mm: 1; SizeX_mm: 1.6; SizeY_mm: 0.8; SizeArea_mm2: 1.28; AEC Category: Q200
C47 = CMP-0007873-2: CAP, CERM, 1 uF, 50 V, +/- 10%, X7R, 0805; Manufacturer: TDK; TaMin_C: -55°C; ESR_ohm: 8.782m; Polarized: N; SizeAreaWB_mm2: 6.75; Value1: 0.008782 ohm; U/M: EA; Value: 1uF; TaMax_C: 125°C; SizeZ_mm: 1.45; SizeX_mm: 2; SizeY_mm: 1.25; Cap_Case: 0805; SizeArea_mm2: 2.5; IRMS_A: 2.20488A; AEC Category: Q200
D11 D21 = CMP-0005718-3: Diode, TVS, Uni, 60 V, SMC; Manufacturer: Fairchild Semiconductor; SizeArea_mm2: 50.5686; Value1: 1500W; SizeZ_mm: 2.6; SizeY_mm: 6.22; SizeAreaWB_mm2: 83.2686; Ppk: 1.5kW; SizeX_mm: 8.13; AEC Category: Q101
D12 D19 = CMP-0029196-2: Diode, Ultrafast, 100 V, 2 A, SMA; Manufacturer: ON Semiconductor; SizeX_mm: 5.59; TJmax_C: 175°C; SizeAreaWB_mm2: 37.3428; Io_A: 2A; Green_REACh: Passed; SizeY_mm: 2.92; Value: 100V; Green_Lifecycle: Active; AEC Qualified: N; SizeArea_mm2: 16.3228; AEC Category: Q101; SizeZ_mm: 2.87
D13-D16 D20 D22 = CMP-0076981-2: Diode, Switching, 100 V, 0.2 A, SOD-123; Manufacturer: ON Semiconductor; Value1: 0.2A; Io_A: 200mA; TJmax_C: 150°C; Green_REACh: Incomplete; SizeY_mm: 1.7; Green_Lifecycle: Not Set; Vr_V: 100V; Value: 100V; SizeZ_mm: 1.35; AEC Category: Q101; SizeAreaWB_mm2: 13.095; SizeX_mm: 3.85; SizeArea_mm2: 6.545
D17 D18 = CMP-0005751-4: Diode, Zener, 12 V, 500 mW, SOD-123; Manufacturer: Diodes Inc.; RJA_CperW: 350; SizeZ_mm: 1.35; SizeAreaWB_mm2: 13.095; AEC Category: Q101; SizeArea_mm2: 6.545; Power_W: 500mW; Value1: 0.5W; SizeY_mm: 1.7; SizeX_mm: 3.85
D23 = CMP-0028456-1: Diode, Schottky, 30 V, 0.2 A, SOT-23; Manufacturer: Diodes Inc.; Io_A: 200mA; Green_Lifecycle: Active; SizeAreaWB_mm2: 14; Vr_V: 30V; Green_REACh: Passed; Value1: 0.2A; TJmax_C: 125°C; U/M: EA; Value: 30V; SizeZ_mm: 1.1; SizeX_mm: 2.5; SizeY_mm: 3; Vf_V: 650mV; Value2: 0.65V; SizeArea_mm2: 7.5; AEC Category: Q101
D24 = CMP-0028411-2: Diode, Schottky, 100 V, 3 A, SMC; Manufacturer: Diodes Inc.; SizeZ_mm: 2.6; Vf_V: 790mV; RJC_CperW: 10; Value2: 0.79V; Io_A: 3A; SizeAreaWB_mm2: 83.2686; SizeY_mm: 6.22; Green_REACh: Passed; TJmax_C: 125°C; SizeX_mm: 8.13; AEC Category: Q101; SizeArea_mm2: 50.5686; Value: 100V; Green_Lifecycle: Active
D25-D27 = CMP-0002892-3: LED, Yellow, SMD; Manufacturer: Wurth Elektronik; Value1: W; Vf_V: 2V; Type: AlInGaP; Io_A: 20mA
J6 = CMP-0074913-1: Terminal Block, 3.5mm Pitch, 2x1, TH; Manufacturer: On-Shore Technology; Cert_VDE: Y; CNHeader: False; Current_A: 6A; Green_Lifecycle: Active; Shrouded: N; Gender: Female; Green_REACh: Passed; Voltage_V: 150V; Row_Count: 1; Pitch_mm: 3.5; ContactFinish: Brass; CT: True
J7 J9 J10 = CMP-0054952-1: Header, 100mil, 2x1, Tin, TH; Manufacturer: TE Connectivity; CNHeader: TRUE; Green_Lifecycle: Active; Green_REACh: Passed; CT: FALSE
J8 J11 = CMP-0054951-1: Header, 100mil, 3x1, Tin, TH; Manufacturer: TE Connectivity; CNHeader: TRUE; Green_Lifecycle: Active; Green_REACh: Passed; CT: FALSE
L7 = CMP-0063967-1: Inductor, Shielded Drum Core, Superflux, 5.5 uH, 10 A, 0.0112 ohm, SMD; Manufacturer: Wurth Elektronik; Isat: 12A @ 30% inductance drop; Irms: 10A @ 50C rise; Green_Lifecycle: Active; SizeAreaWB_mm2: 158.6; DCR_ohm: 0.0112; Green_REACh: Passed; Value: 5.5uH; Imax_A: 10A; SizeZ_mm: 5; SizeX_mm: 11; SizeY_mm: 10.2; SizeArea_mm2: 112.2; Ind_H: 5.5µH; AEC Category: Q200
L8 = CMP-0064477-2: Inductor, Shielded Drum Core, Ferrite, 15 uH, 14 A, 0.009 ohm, SMD; Manufacturer: Wurth Elektronik; Isat: 14A @ 30% inductance drop; Irms: 14A @ 50C rise; Green_Lifecycle: Active; SizeAreaWB_mm2: 410.06; DCR_ohm: 9m; Green_REACh: Passed; Value: 15uH; Imax_A: 14A; SizeZ_mm: 9.2; SizeX_mm: 18.3; SizeY_mm: 18.2; SizeArea_mm2: 333.06; Ind_H: 15µH; AEC Category: Q200
L9 = CMP-0064865-2: Inductor, Unshielded Drum Core, Metal Composite, 2.2 mH, 0.15 A, 6 ohm, SMD; Manufacturer: Wurth Elektronik; Isat: 0.2A @ 10% inductance drop; Irms: 0.15A @ 40C rise; Green_Lifecycle: Active; SizeAreaWB_mm2: 88.2; DCR_ohm: 6; Green_REACh: Passed; Value1: 6 ohm; Value: 2.2mH; Imax_A: 150mA; SizeZ_mm: 5; SizeX_mm: 7; SizeY_mm: 7.8; Value2: 0.15A; SizeArea_mm2: 54.6; AEC Category: Q200
Q5 Q7 = CMP-0000415-2: Transistor, NPN, 100 V, 1 A, SOT-89; Manufacturer: Diodes Inc.; TaMax_C: 150°C; Value2: 300; Value1: 1 A; Vcesat1_V: 600mV; SizeX_mm: 4.1; SizeY_mm: 4.5; TaMin_C: -65°C; IcRated_A: 1A; CompType: BJT; SizeZ_mm: 1.5; Value: 100 V; SizeArea_mm2: 18.45; NPN: 1; Vceo_V: 100V; PNP: 0; AEC Category: Q101; SizeAreaWB_mm2: 28.05; U/M: EA
Q6 Q8 = CMP-0000939-2: MOSFET, N-CH, 100 V, 90 A, PG-TDSON-8; Alternate Manufacturer: None; Manufacturer: Infineon Technologies; SizeZ_mm: 1.12; ChType: N; Value2: 40 nC; Value1: 0.014; VdsMax_V: 100V; SizeX_mm: 5.99; SizeY_mm: 4.9; Vgs_V: 20V; Value: 100V; Rdson45_ohm: 0.0141; SizeArea_mm2: 29.351; AEC Category: Q101; IdsMax_A: 90A; SizeAreaWB_mm2: 55.131; U/M: EA; QgTyp_nC: 40
Q9 = CMP-0086360-1: MOSFET, P-CH, -80 V, -2.2 A, AEC-Q101, SOT-23; Manufacturer: Vishay-Siliconix; Alternate Manufacturer: None; Value1: ? ohm; SizeX_mm: 2.5; Value2: 11.5 nC; AEC Qualified: Y; VdsMax_V: -80V; SizeY_mm: 3; IdsMax_A: -2.2A; Vgs_V: -20V; ChType: P; SizeZ_mm: 1.1; Value: -80V; ChMode: Enhancement; SizeAreaWB_mm2: 14; SizeArea_mm2: 7.5; AEC Category: Q101; QgTyp_nC: 11.5
Q10 = CMP-0000056-3: MOSFET, P-CH, -150 V, -3 A, QFN-8; Alternate Manufacturer: None; Manufacturer: Fairchild Semiconductor; ChType: P; VdsMax_V: -150V; AEC Category: Q101; Value2: 6.2 nC; SizeAreaWB_mm2: 18.49; QgTyp_nC: 6.2; Value: -150V; SizeZ_mm: 0.8; ChMode: Enhancement; AEC Qualified: N; IdsMax_A: -3A; SizeX_mm: 3.3; SizeArea_mm2: 10.89; Vgs_V: -30V
Q11 = CMP-0001057-1: MOSFET, N-CH, 150 V, 6.7 A, PQFN08A; Alternate Manufacturer: None; Manufacturer: Fairchild Semiconductor; SizeZ_mm: 1.1; ChType: N; Value2: 36 nC; Value1: 0.02; VdsMax_V: 150V; SizeX_mm: 5; SizeY_mm: 6; Vgs_V: 4V; Value: 150V; Rdson45_ohm: 0.025; SizeArea_mm2: 30; AEC Category: Q101; IdsMax_A: 6.7A; SizeAreaWB_mm2: 56; U/M: EA; QgTyp_nC: 36
Q12 = CMP-0001066-3: MOSFET, N-CH, 150 V, 2.7 A, SOIC-8; Alternate Manufacturer: None; Manufacturer: Vishay-Siliconix; SizeZ_mm: 1.75; ChType: N; Value2: 17 nC; Value1: 0.07; VdsMax_V: 150V; SizeX_mm: 5.99; SizeY_mm: 4.9; Vgs_V: 20V; Value: 150V; Rdson45_ohm: 0.076; SizeArea_mm2: 29.351; AEC Category: Q101; IdsMax_A: 2.7A; SizeAreaWB_mm2: 55.131; U/M: EA; QgTyp_nC: 17
R25 = CMP-0022008-4: RES, 110 k, 1%, 0.1 W, AEC-Q200 Grade 0, 0603; Manufacturer: Vishay-Dale; Power_W: 100mW; TempCo: 100 ppm/C; Value: 110k; EIA_Code: E96; SizeX_mm: 1.6; SizeY_mm: 0.8; SizeZ_mm: 1; Value2: 0.1W; SizeArea_mm2: 1.28; AEC Qualified: Y; VDC_V: 75V; AEC Category: Q200; AEC Grade: 0
R26 R36 R44 R56-R61 = CMP-0021998-4: RES, 10.0 k, 1%, 0.1 W, AEC-Q200 Grade 0, 0603; Manufacturer: Vishay-Dale; Power_W: 100mW; TempCo: 100 ppm/C; Value_Code: 10k0; Value: 10.0k; EIA_Code: E96; Res_ohm: 10k; SizeX_mm: 1.6; SizeY_mm: 0.8; SizeZ_mm: 1; Value2: 0.1W; SizeArea_mm2: 1.28; AEC Qualified: Y; VDC_V: 75V; AEC Category: Q200; AEC Grade: 0
R27 R35 = CMP-0015868-3: RES, 10 k, 5%, 1 W, AEC-Q200 Grade 0, 2512; Manufacturer: Vishay-Dale; Power_W: 1W; TempCo: 200 ppm/C; Value_Code: 10k0; Value: 10k; EIA_Code: E24; SizeX_mm: 6.3; SizeY_mm: 3.2; SizeZ_mm: 0.71; SizeArea_mm2: 20.16; AEC Qualified: Y; VDC_V: 500V; AEC Grade: 0; AEC Category: Q200
R28 = CMP-0015867-3: RES, 100, 5%, 1 W, AEC-Q200 Grade 0, 2512; Manufacturer: Vishay-Dale; Power_W: 1W; TempCo: 200 ppm/C; Value_Code: 100R; Value: 100; EIA_Code: E24; SizeX_mm: 6.3; SizeY_mm: 3.2; SizeZ_mm: 0.71; SizeArea_mm2: 20.16; AEC Qualified: Y; VDC_V: 500V; AEC Grade: 0; AEC Category: Q200
R29 = CMP-0017020-3: RES, 4.02 k, 1%, 0.25 W, AEC-Q200 Grade 0, 1206; Manufacturer: Vishay-Dale; Power_W: 250mW; TempCo: 100 ppm/C; Value_Code: 4k02; Value: 4.02k; EIA_Code: E96; SizeX_mm: 3.2; SizeY_mm: 1.6; SizeZ_mm: 1.35; Value2: 0.25W; SizeArea_mm2: 5.12; AEC Qualified: Y; VDC_V: 200V; AEC Category: Q200; AEC Grade: 0
R30 = CMP-0022004-4: RES, 10.0, 1%, 0.25 W, AEC-Q200 Grade 0, 0603; Manufacturer: Vishay-Dale; Power_W: 250mW; TempCo: 100 ppm/C; Value_Code: 10R0; Value: 10.0; EIA_Code: E96; Res_ohm: 10; SizeX_mm: 1.6; SizeY_mm: 0.8; SizeZ_mm: 1; Value2: 0.25W; SizeArea_mm2: 1.28; AEC Qualified: Y; VDC_V: 75V; AEC Category: Q200; AEC Grade: 0
R31 = CMP-0025768-4: RES, 2.0 k, 5%, 0.1 W, AEC-Q200 Grade 0, 0603; Manufacturer: Vishay-Dale; Power_W: 100mW; TempCo: 200 ppm/C; Value_Code: 2k00; Value: 2.0k; EIA_Code: E24; Res_ohm: 2k; SizeX_mm: 1.6; SizeY_mm: 0.8; SizeZ_mm: 1; Value2: 0.1W; SizeArea_mm2: 1.28; AEC Qualified: Y; VDC_V: 75V; AEC Category: Q200; AEC Grade: 0
R32 = CMP-0017203-3: RES, 8.06 k, 1%, 0.25 W, AEC-Q200 Grade 0, 1206; Manufacturer: Vishay-Dale; Power_W: 250mW; TempCo: 100 ppm/C; Value_Code: 8k06; Value: 8.06k; EIA_Code: E96; SizeX_mm: 3.2; SizeY_mm: 1.6; SizeZ_mm: 1.35; Value2: 0.25W; SizeArea_mm2: 5.12; AEC Qualified: Y; VDC_V: 200V; AEC Category: Q200; AEC Grade: 0
R33 = CMP-0021833-2: RES, 5.10, 1%, 0.125 W, AEC-Q200 Grade 0, 0805; Manufacturer: Panasonic; Power_W: 125mW; TempCo: 200 ppm/C; Value_Code: 5R10; U/M: EA; Value: 5.10; Res_ohm: 5.1; SizeX_mm: 2; SizeY_mm: 1.25; SizeZ_mm: 1.45; Value2: 0.125W; SizeArea_mm2: 2.5; AEC Qualified: Y; AEC Grade: 0; AEC Category: Q200
R34 = CMP-0022931-4: RES, 237 k, 1%, 0.1 W, 0603; Manufacturer: Yageo; Power_W: 100mW; TempCo: 100 ppm/C; Value: 237k; EIA_Code: E96; SizeX_mm: 1.6; SizeY_mm: 0.8; SizeZ_mm: 1; Value2: 0.1W; SizeArea_mm2: 1.28; AEC Qualified: N; VDC_V: 75V; AEC Category: Q200; SizeAreaWB_mm2: 4.68
R37 = CMP-0022532-4: RES, 60.4 k, 1%, 0.1 W, AEC-Q200 Grade 0, 0603; Manufacturer: Vishay-Dale; Power_W: 100mW; TempCo: 100 ppm/C; Value_Code: 60k4; Value: 60.4k; EIA_Code: E96; SizeX_mm: 1.6; SizeY_mm: 0.8; SizeZ_mm: 1; Value2: 0.1W; SizeArea_mm2: 1.28; AEC Qualified: Y; VDC_V: 75V; AEC Category: Q200; AEC Grade: 0
R38 = CMP-0022003-1: RES, 10.0, 1%, 0.1 W, 0603; Manufacturer: Vishay-Dale; Power_W: 100mW; TempCo: 100 ppm/C; Value_Code: 10R0; U/M: EA; Value: 10.0; EIA_Code: E96; Res_ohm: 10; SizeX_mm: 1.6; SizeY_mm: 0.8; SizeZ_mm: 1; Value2: 0.1W; SizeArea_mm2: 1.28; VDC_V: 75V; AEC Category: Q200
R39 = CMP-0023143-5: RES, 49.9, 1%, 0.1 W, 0603; Manufacturer: Yageo; Power_W: 100mW; TempCo: 100 ppm/C; Value_Code: 49R9; Value: 49.9; EIA_Code: E96; SizeX_mm: 1.6; SizeY_mm: 0.8; SizeZ_mm: 1; Value2: 0.1W; SizeArea_mm2: 1.28; AEC Qualified: N; VDC_V: 75V; AEC Category: Q200; SizeAreaWB_mm2: 4.68
R40 = CMP-0022447-4: RES, 49.9 k, 1%, 0.1 W, AEC-Q200 Grade 0, 0603; Manufacturer: Vishay-Dale; Power_W: 100mW; TempCo: 100 ppm/C; Value_Code: 49k9; Value: 49.9k; EIA_Code: E96; SizeX_mm: 1.6; SizeY_mm: 0.8; SizeZ_mm: 1; Value2: 0.1W; SizeArea_mm2: 1.28; AEC Qualified: Y; VDC_V: 75V; AEC Category: Q200; AEC Grade: 0
R41 R46 = CMP-0022268-4: RES, 2.00 k, 1%, 0.1 W, AEC-Q200 Grade 0, 0603; Manufacturer: Vishay-Dale; Power_W: 100mW; TempCo: 100 ppm/C; Value_Code: 2k00; Value: 2.00k; EIA_Code: E96; Res_ohm: 2k; SizeX_mm: 1.6; SizeY_mm: 0.8; SizeZ_mm: 1; Value2: 0.1W; SizeArea_mm2: 1.28; AEC Qualified: Y; VDC_V: 75V; AEC Category: Q200; AEC Grade: 0
R42 = CMP-0023345-2: RES, 2.00 k, 1%, 0.1 W, 0603; Manufacturer: Vishay Foil Resistors; Power_W: 100mW; TempCo: 0.2 ppm/C; Value_Code: 2k00; U/M: EA; Value: 2.00k; EIA_Code: E96; Res_ohm: 2k; SizeX_mm: 1.6; SizeY_mm: 0.81; SizeZ_mm: 0.64; Value2: 0.1W; SizeArea_mm2: 1.296; AEC Qualified: N; VDC_V: 20V; AEC Category: Q200
R43 = CMP-0022446-5: RES, 499, 1%, 0.1 W, AEC-Q200 Grade 0, 0603; Manufacturer: Vishay-Dale; Power_W: 100mW; TempCo: 100 ppm/C; Value_Code: 499R; Value: 499; EIA_Code: E96; SizeX_mm: 1.6; SizeY_mm: 0.8; SizeZ_mm: 1; Value2: 0.1W; SizeArea_mm2: 1.28; AEC Qualified: Y; VDC_V: 75V; AEC Category: Q200; AEC Grade: 0
R45 = CMP-0022410-4: RES, 40.2 k, 1%, 0.1 W, AEC-Q200 Grade 0, 0603; Manufacturer: Vishay-Dale; Power_W: 100mW; TempCo: 100 ppm/C; Value_Code: 40k2; Value: 40.2k; EIA_Code: E96; SizeX_mm: 1.6; SizeY_mm: 0.8; SizeZ_mm: 1; Value2: 0.1W; SizeArea_mm2: 1.28; AEC Qualified: Y; VDC_V: 75V; AEC Category: Q200; AEC Grade: 0
R47 = CMP-0021169-3: RES, 31.6, 1%, 0.125 W, AEC-Q200 Grade 0, 0805; Manufacturer: Vishay-Dale; Power_W: 125mW; TempCo: 100 ppm/C; Value_Code: 31R6; Value: 31.6; EIA_Code: E96; SizeX_mm: 2; SizeY_mm: 1.25; SizeZ_mm: 1.45; Value2: 0.125W; SizeArea_mm2: 2.5; AEC Qualified: Y; VDC_V: 150V; AEC Category: Q200; AEC Grade: 0
R48 = CMP-0022109-1: RES, 1.00 k, 1%, 0.1 W, 0603; Manufacturer: Vishay-Dale; Power_W: 100mW; TempCo: 100 ppm/C; Value_Code: 1k00; U/M: EA; Value: 1.00k; EIA_Code: E96; Res_ohm: 1k; SizeX_mm: 1.6; SizeY_mm: 0.8; SizeZ_mm: 1; Value2: 0.1W; SizeArea_mm2: 1.28; VDC_V: 75V; AEC Category: Q200
R49 = CMP-0020868-3: RES, 121, 1%, 0.125 W, AEC-Q200 Grade 0, 0805; Manufacturer: Vishay-Dale; Power_W: 125mW; TempCo: 100 ppm/C; Value_Code: 121R; Value: 121; EIA_Code: E96; SizeX_mm: 2; SizeY_mm: 1.25; SizeZ_mm: 1.45; Value2: 0.125W; SizeArea_mm2: 2.5; AEC Qualified: Y; VDC_V: 150V; AEC Category: Q200; AEC Grade: 0
R50 = CMP-0023091-5: RES, 3.00 k, 1%, 0.1 W, 0603; Manufacturer: Yageo; Power_W: 100mW; TempCo: 100 ppm/C; Value_Code: 3k00; Value: 3.00k; Res_ohm: 3k; SizeX_mm: 1.6; SizeY_mm: 0.8; SizeZ_mm: 1; Value2: 0.1W; SizeArea_mm2: 1.28; AEC Qualified: N; VDC_V: 75V; AEC Category: Q200; SizeAreaWB_mm2: 4.68
R51 = CMP-0022965-5: RES, 27.4 k, 1%, 0.1 W, 0603; Manufacturer: Yageo; Power_W: 100mW; TempCo: 100 ppm/C; Value_Code: 27k4; Value: 27.4k; EIA_Code: E96; SizeX_mm: 1.6; SizeY_mm: 0.8; SizeZ_mm: 1; Value2: 0.1W; SizeArea_mm2: 1.28; AEC Qualified: N; VDC_V: 75V; AEC Category: Q200; SizeAreaWB_mm2: 4.68
R52 = CMP-0017281-2: RES, 0.05, 1%, 1 W, AEC-Q200 Grade 0, 1206; Manufacturer: Panasonic; SizeZ_mm: 1.35; Value2: 1W; SizeArea_mm2: 5.12; AEC Qualified: Y; AEC Grade: 0; AEC Category: Q200; TempCo: 50 ppm/C; Value_Code: R050; U/M: EA; Value: 0.05; EIA_Code: E96; SizeX_mm: 3.2; SizeY_mm: 1.6
R53 = CMP-0022000-4: RES, 10.5 k, 1%, 0.1 W, AEC-Q200 Grade 0, 0603; Manufacturer: Vishay-Dale; Power_W: 100mW; TempCo: 100 ppm/C; Value_Code: 10k5; Value: 10.5k; EIA_Code: E96; SizeX_mm: 1.6; SizeY_mm: 0.8; SizeZ_mm: 1; Value2: 0.1W; SizeArea_mm2: 1.28; AEC Qualified: Y; VDC_V: 75V; AEC Category: Q200; AEC Grade: 0
R54 = CMP-0022418-4: RES, 42.2 k, 1%, 0.1 W, AEC-Q200 Grade 0, 0603; Manufacturer: Vishay-Dale; Power_W: 100mW; TempCo: 100 ppm/C; Value_Code: 42k2; Value: 42.2k; EIA_Code: E96; SizeX_mm: 1.6; SizeY_mm: 0.8; SizeZ_mm: 1; Value2: 0.1W; SizeArea_mm2: 1.28; AEC Qualified: Y; VDC_V: 75V; AEC Category: Q200; AEC Grade: 0
R55 = CMP-0022445-4: RES, 499 k, 1%, 0.1 W, AEC-Q200 Grade 0, 0603; Manufacturer: Vishay-Dale; Power_W: 100mW; TempCo: 100 ppm/C; Value: 499k; EIA_Code: E96; SizeX_mm: 1.6; SizeY_mm: 0.8; SizeZ_mm: 1; Value2: 0.1W; SizeArea_mm2: 1.28; AEC Qualified: Y; VDC_V: 75V; AEC Category: Q200; AEC Grade: 0
R62-R64 = CMP-0021998-4: RES, 10.0 k, 1%, 0.1 W, AEC-Q200 Grade 0, 0603; Manufacturer: Vishay-Dale; CompType: Resistor; Value: 10.0k; Res_ohm: 10k; Value_Code: 10k0; Power_W: 100mW; Value2: 0.1W; VDC_V: 75V; TempCo: 100 ppm/C; SizeArea_mm2: 1.28; SizeX_mm: 1.6; SizeY_mm: 0.8; SizeZ_mm: 1; EIA_Code: E96; AEC Category: Q200; AEC Qualified: Y; AEC Grade: 0
T2 = CMP-0087896-1: Power Over Ethernet (PoE) For Configurable (For DC/DC) SMPS Transformer 1500Vrms Isolation Surface Mount; Manufacturer: Wurth Electronics; SizeZ_mm: 11.43mm; DCR_ohm: 0.065; AEC Qualified: No; Ind_H: 100µH; Ns1toNp: 2:1/2:1/2:1/2:1
TP12-TP17 TP21 TP23 TP24 TP27 TP28 TP30-TP32 TP36 = CMP-0055137-1: Test Point, Miniature, Red, TH; Manufacturer: Keystone; CNHeader: FALSE; Green_Lifecycle: Active; Green_REACh: Passed; ContactFinish: Silver; CT: TRUE
TP18-TP20 TP29 TP35 TP38-TP40 TP42 = CMP-0055138-1: Test Point, Miniature, Black, TH; Manufacturer: Keystone; CNHeader: FALSE; Green_Lifecycle: Active; Green_REACh: Passed; ContactFinish: Silver; CT: TRUE
TP22 TP25 TP26 TP33 TP37 TP41 = CMP-0055139-1: Test Point, Miniature, White, TH; Manufacturer: Keystone; CNHeader: FALSE; Green_Lifecycle: Active; Green_REACh: Passed; ContactFinish: Silver; CT: TRUE
TP34 TP43-TP48 = CMP-0055140-1: Test Point, Miniature, Orange, TH; Manufacturer: Keystone; CNHeader: FALSE; Green_Lifecycle: Active; Green_REACh: Passed; ContactFinish: Silver; CT: TRUE
U1 = CMP-0860918-1: TPS23730RMT, RMT0045A (VQFN-45); Alternate Manufacturer: Texas Instruments; SizeArea_mm2: 35; CompType: IC; SizeY_mm: 7; SizeAreaWB_mm2: 63; AEC Category: Q200; SizeZ_mm: 1; AEC Qualified: N; SizeX_mm: 5
U2 = CMP-0006166-3: Optocoupler, 3.75 kV, 80-160% CTR, SMT; Manufacturer: Vishay-Semiconductor; CTR (Max): 160%; SizeAreaWB_mm2: 43.65; CTR (Min): 80%; SizeZ_mm: 2.3; SizeX_mm: 7; SizeY_mm: 2.85; SizeArea_mm2: 19.95; Voltage_Isolation_Vrms: 3.75kV
U3 = CMP-0032888-1: Adjustable Precision Shunt Regulator, 34 ppm / degC, 100 mA, -40 to 85 degC, 5-pin SOT-23 (DBV), Green (RoHS & no Sb/Br); Manufacturer: Texas Instruments; Rating: Military; Initial Accuracy @ 25/deg C(%): 2; Iout/Iz(Max)(mA): 100; Min Iz for Regulation(uA): 600; SubFamily: Shunt Voltage Reference; Temp Coeff(Max)(ppm/ degree C): 92; Temp Coeff(Typ)(ppm/ degree C): 34; VO Adj(Max)(V): 36; VO Adj(Min)(V): 2.495
U4-U6 = CMP-0006165-3: Optocoupler, 5 kV, 300-600% CTR, SMT; Manufacturer: Fairchild Semiconductor; CTR (Min): 300%; CTR (Max): 600%; Voltage_Isolation_Vrms: 5kV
